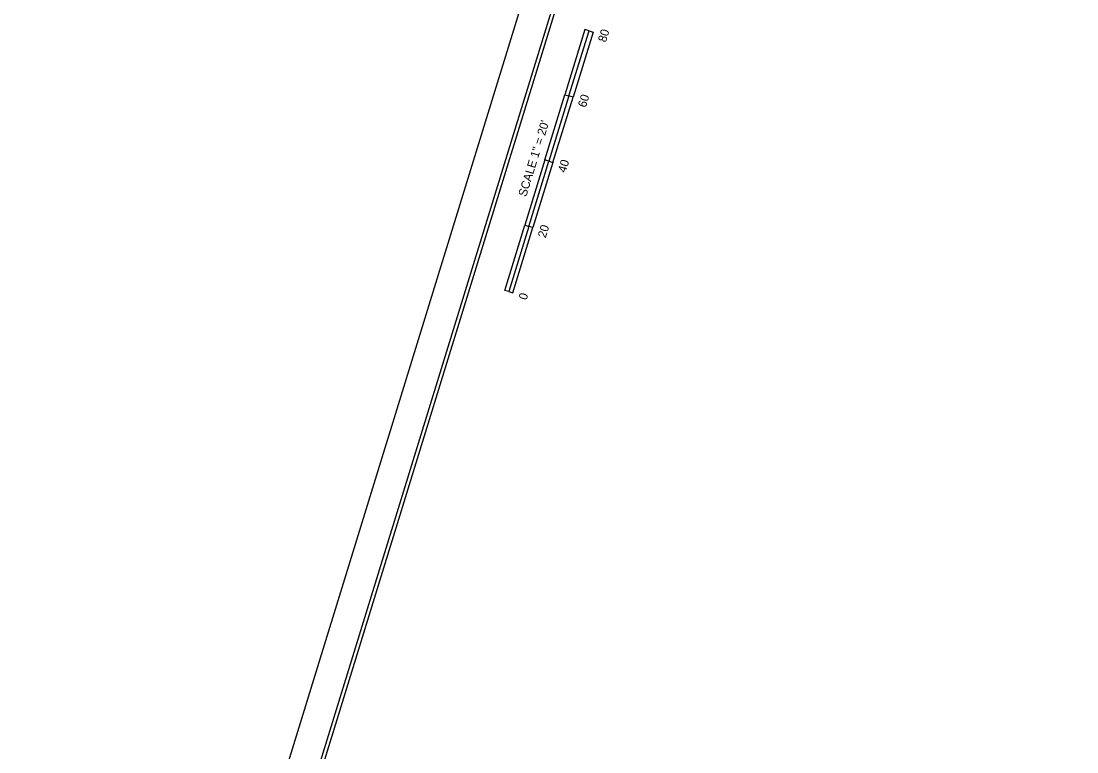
# Model space of a CAD drawing. Extents: x 1439200 to 1642353, y 394562 to 606444.
# Drawn here: x 1641734.9 to 1642044.2, y 394948.2 to 395162.5 of the extents above; entities that cross this region are included whole.
import ezdxf

# ---------------------------------------------------------------- set-up
doc = ezdxf.new("R2010")
doc.units = 0
for name, color, linetype in [('Old_Level_20', 7, 'Continuous'), ('Sheet Plot Border Inside CELL', 7, 'Continuous'), ('Sheet Plot Border Outside CELL', 7, 'Continuous'), ('UC Plan Sheet 34 CELL', 7, 'Continuous')]:
    doc.layers.add(name, color=color, linetype=linetype)

msp = doc.modelspace()

# ---------------------------------------------------------------- linework, layer by layer
at = {"layer": 'Old_Level_20'}
for points in [[(1641895.4, 395140.53), (1641901.28, 395159.65), (1641900.09, 395160.01), (1641894.21, 395140.9), (1641895.4, 395140.53)], [(1641890.72, 395121.05), (1641896.6, 395140.16), (1641895.4, 395140.53), (1641889.52, 395121.41), (1641890.72, 395121.05)], [(1641883.64, 395102.3), (1641889.52, 395121.41), (1641888.33, 395121.78), (1641882.45, 395102.66), (1641883.64, 395102.3)], [(1641878.96, 395082.81), (1641884.84, 395101.93), (1641883.64, 395102.3), (1641877.76, 395083.18), (1641878.96, 395082.81)]]:
    msp.add_lwpolyline(points, dxfattribs=at)
for points in [[(1641895.4, 395140.53), (1641901.28, 395159.65), (1641902.48, 395159.28), (1641896.6, 395140.16)], [(1641888.33, 395121.78), (1641894.21, 395140.9), (1641895.4, 395140.53), (1641889.52, 395121.41)], [(1641883.64, 395102.3), (1641889.52, 395121.41), (1641890.72, 395121.05), (1641884.84, 395101.93)], [(1641876.57, 395083.55), (1641882.45, 395102.66), (1641883.64, 395102.3), (1641877.76, 395083.18)]]:
    msp.add_lwpolyline(points, close=True, dxfattribs=at)
at = {"layer": 'Sheet Plot Border Inside CELL'}
msp.add_lwpolyline([(1641940.98, 395330.47), (1641745.02, 394693.33), (1642148.41, 394569.26), (1642344.38, 395206.4)], close=True, dxfattribs=at)
at = {"layer": 'Sheet Plot Border Outside CELL'}
msp.add_lwpolyline([(1641932.93, 395334.83), (1641734.91, 394691), (1642155.47, 394561.65), (1642353.49, 395205.48)], close=True, dxfattribs=at)
at = {"layer": 'UC Plan Sheet 34 CELL'}
msp.add_lwpolyline([(1641940.49, 395325.39), (1641764.1, 394751.91), (1642165.54, 394628.44), (1642341.93, 395201.92)], close=True, dxfattribs=at)

# ---------------------------------------------------------------- texts
at = {"layer": 'Old_Level_20'}
for s, p in [('80', (1641906.21, 395156.1)), ('60', (1641900.33, 395136.98)), ('SCALE 1" = 20\'', (1641882.87, 395110.83)), ('40', (1641894.45, 395117.87)), ('20', (1641888.57, 395098.75)), ('0', (1641882.97, 395080.56))]:
    msp.add_text(s, height=2.5, rotation=72.9038, dxfattribs=at).set_placement(p)

doc.saveas('drawing.dxf')
